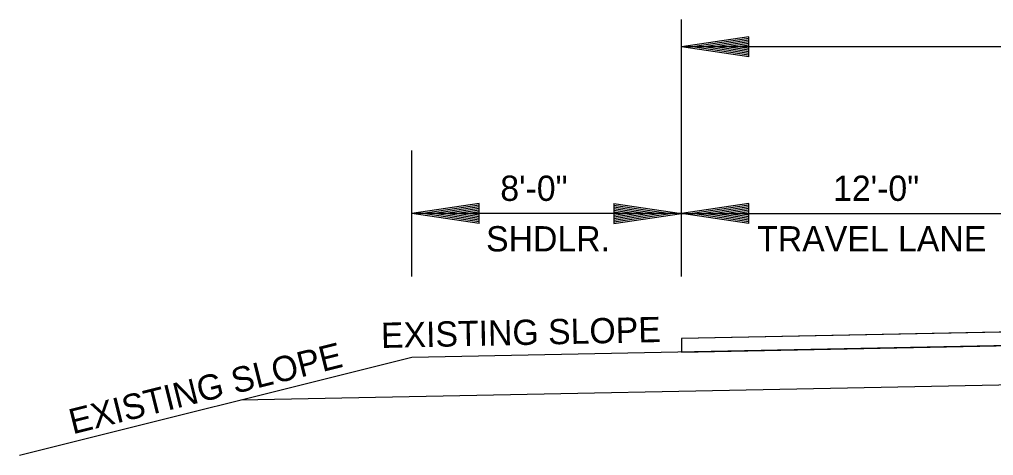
# Model space of a CAD drawing. Extents: x 34757 to 38214, y 51436 to 59430.
# Drawn here: x 36724.6 to 37158.2, y 54042.6 to 54236.8 of the extents above; entities that cross this region are included whole.
import ezdxf

# ---------------------------------------------------------------- set-up
doc = ezdxf.new("R2010")
doc.units = 0
doc.layers.add('Default', color=7, linetype='Continuous')

msp = doc.modelspace()

# ---------------------------------------------------------------- linework, layer by layer
at = {"layer": 'Default'}
for p, q in [((37019.2, 54122.4), (37019.2, 54236.81)), ((37049.2, 54229.15), (37019.2, 54224.65)), ((37049.2, 54220.15), (37049.2, 54229.15)), ((37919.2, 54224.67), (37019.2, 54224.65)), ((37049.2, 54220.15), (37019.2, 54224.65)), ((37049.2, 54228.4), (37024.21, 54224.65)), ((37049.2, 54220.9), (37024.21, 54224.65)), ((37049.2, 54227.63), (37029.37, 54224.65)), ((37049.2, 54221.66), (37029.37, 54224.65)), ((37049.2, 54226.88), (37034.37, 54224.65)), ((37049.2, 54222.41), (37034.37, 54224.65)), ((37049.2, 54226.12), (37039.45, 54224.65)), ((37049.2, 54223.19), (37039.45, 54224.65)), ((37049.2, 54225.35), (37044.46, 54224.65)), ((37049.2, 54223.94), (37044.46, 54224.65)), ((36899.2, 54122.4), (36899.2, 54178.38)), ((37019.2, 54122.4), (37019.2, 54178.38)), ((36929.2, 54154.89), (36899.2, 54150.39)), ((36929.2, 54154.14), (36904.21, 54150.39)), ((36929.2, 54153.37), (36909.37, 54150.39)), ((36929.2, 54152.62), (36914.37, 54150.39)), ((36929.2, 54151.86), (36919.45, 54150.39)), ((36929.2, 54151.09), (36924.46, 54150.39)), ((36929.2, 54145.89), (36929.2, 54154.89)), ((36989.2, 54154.89), (37019.2, 54150.39)), ((36989.2, 54154.89), (36989.2, 54145.89)), ((36989.2, 54154.14), (37014.19, 54150.39)), ((36989.2, 54153.37), (37009.03, 54150.39)), ((36989.2, 54152.62), (37004.04, 54150.39)), ((36989.2, 54151.84), (36998.95, 54150.39)), ((36989.2, 54151.09), (36993.94, 54150.39)), ((37049.2, 54154.89), (37019.2, 54150.39)), ((37049.2, 54154.14), (37024.21, 54150.39)), ((37049.2, 54153.37), (37029.37, 54150.39)), ((37049.2, 54152.62), (37034.37, 54150.39)), ((37049.2, 54151.86), (37039.45, 54150.39)), ((37049.2, 54151.09), (37044.46, 54150.39)), ((37049.2, 54145.89), (37049.2, 54154.89)), ((37019.2, 54150.39), (36899.2, 54150.39)), ((36929.2, 54145.89), (36899.2, 54150.39)), ((36929.2, 54146.64), (36904.21, 54150.39)), ((36929.2, 54147.4), (36909.37, 54150.39)), ((36929.2, 54148.15), (36914.37, 54150.39)), ((36929.2, 54148.93), (36919.45, 54150.39)), ((36929.2, 54149.68), (36924.46, 54150.39)), ((36989.2, 54145.89), (37019.2, 54150.39)), ((36989.2, 54148.92), (36998.95, 54150.39)), ((36989.2, 54147.4), (37009.03, 54150.39)), ((36989.2, 54146.64), (37014.19, 54150.39)), ((36989.2, 54148.15), (37004.04, 54150.39)), ((36989.2, 54149.68), (36993.94, 54150.39)), ((37019.2, 54150.39), (37199.2, 54150.39)), ((37049.2, 54145.89), (37019.2, 54150.39)), ((37049.2, 54146.64), (37024.21, 54150.39)), ((37049.2, 54147.4), (37029.37, 54150.39)), ((37049.2, 54148.15), (37034.37, 54150.39)), ((37049.2, 54148.93), (37039.45, 54150.39)), ((37049.2, 54149.68), (37044.46, 54150.39)), ((37469.2, 54103.65), (37019.2, 54094.65)), ((37019.2, 54094.65), (37019.2, 54088.65)), ((36899.2, 54086.25), (36724.58, 54042.59)), ((37469.2, 54080.15), (36823.1, 54067.23))]:
    msp.add_line(p, q, dxfattribs=at)
msp.add_lwpolyline([(37019.2, 54094.65), (37019.2, 54088.65), (37469.2, 54097.65), (37919.2, 54088.65), (37919.2, 54094.65), (37469.2, 54103.65)], close=True, dxfattribs=at)
msp.add_lwpolyline([(37469.2, 54097.65), (36899.2, 54086.25)], dxfattribs=at)

# ---------------------------------------------------------------- texts
for s, p in [('8\'-0"', (36938.61, 54156.01)), ('12\'-0"', (37086.75, 54156.01)), ('SHDLR.', (36932.27, 54133.51)), ('TRAVEL LANE', (37052.95, 54133.51))]:
    msp.add_text(s, height=11.25, dxfattribs=at).set_placement(p)
for rotation, p in [(1.2244, (36885.61, 54090.49)), (14.0368, (36748.29, 54052))]:
    msp.add_text('EXISTING SLOPE', height=11.25, rotation=rotation, dxfattribs=at).set_placement(p)

doc.saveas('drawing.dxf')
